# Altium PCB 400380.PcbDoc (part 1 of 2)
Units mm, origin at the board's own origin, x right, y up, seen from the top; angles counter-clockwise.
Board outline 48.52 x 76.32 mm, 4 copper layers (Top Layer, Mid-Layer 1, Mid-Layer 2, Bottom Layer), stack 1.542 mm thick; 122 components, 105 nets, 497 pads, 444 vias.
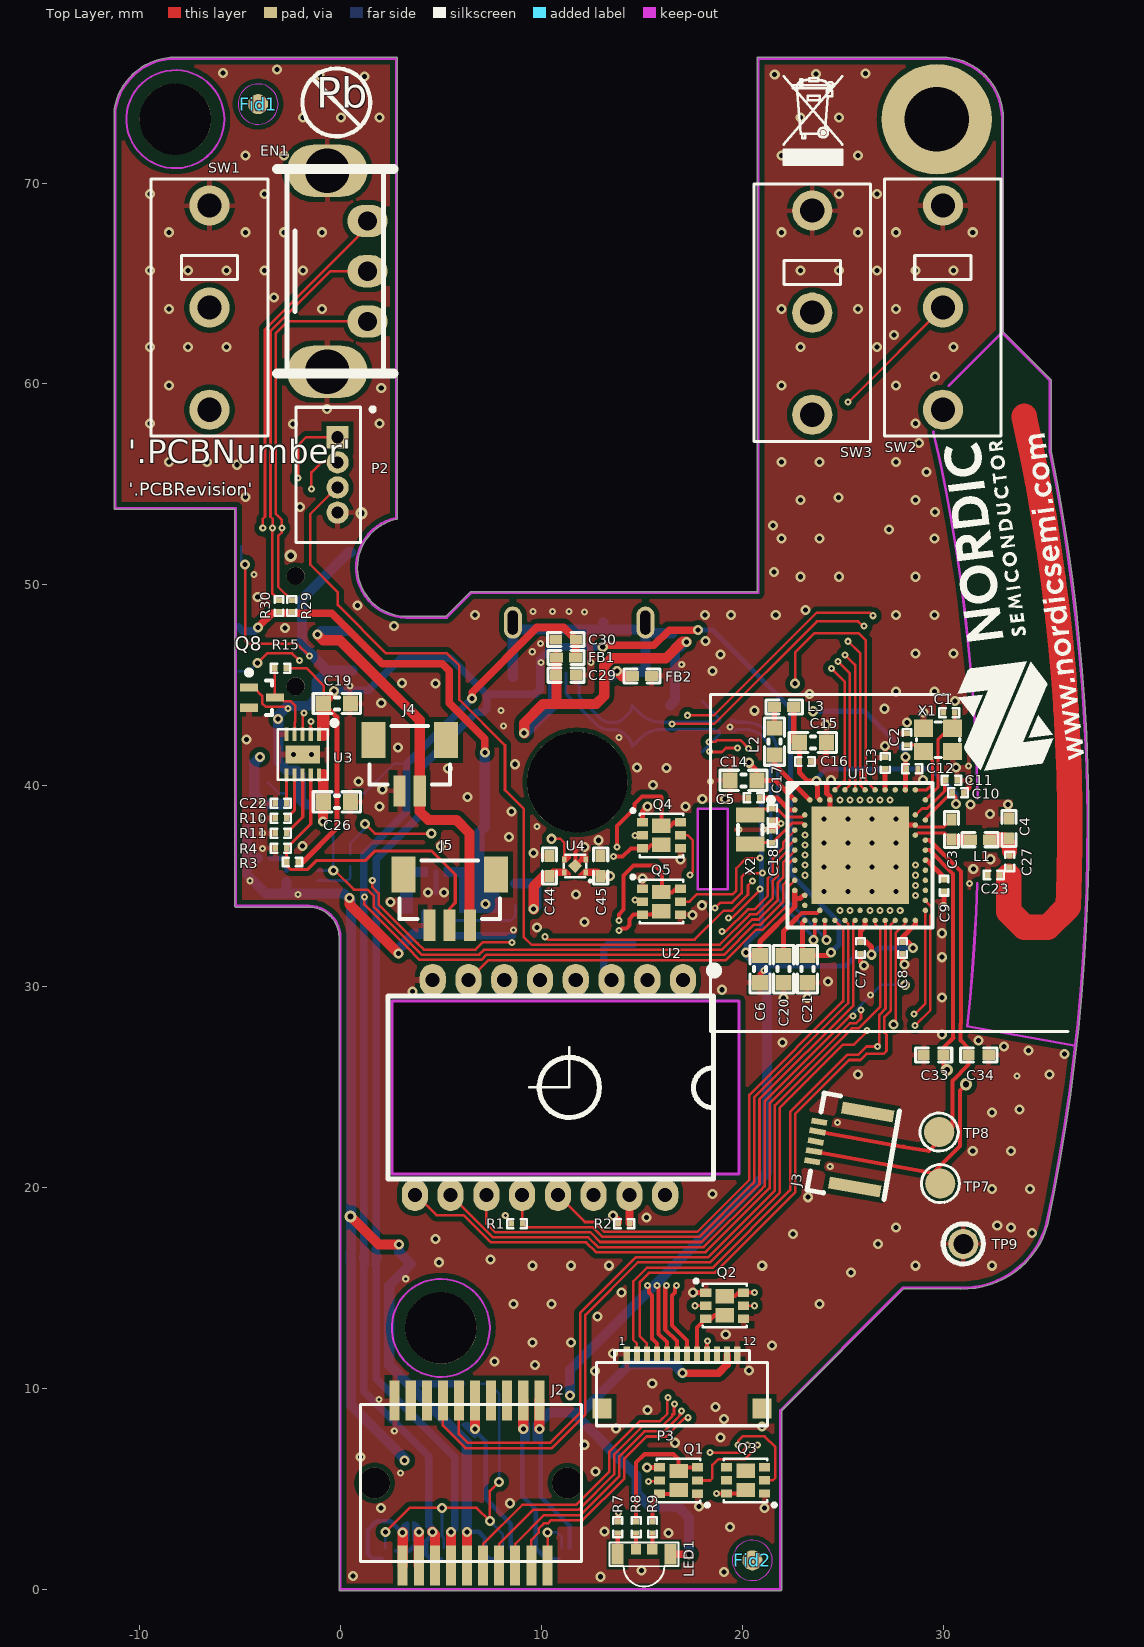
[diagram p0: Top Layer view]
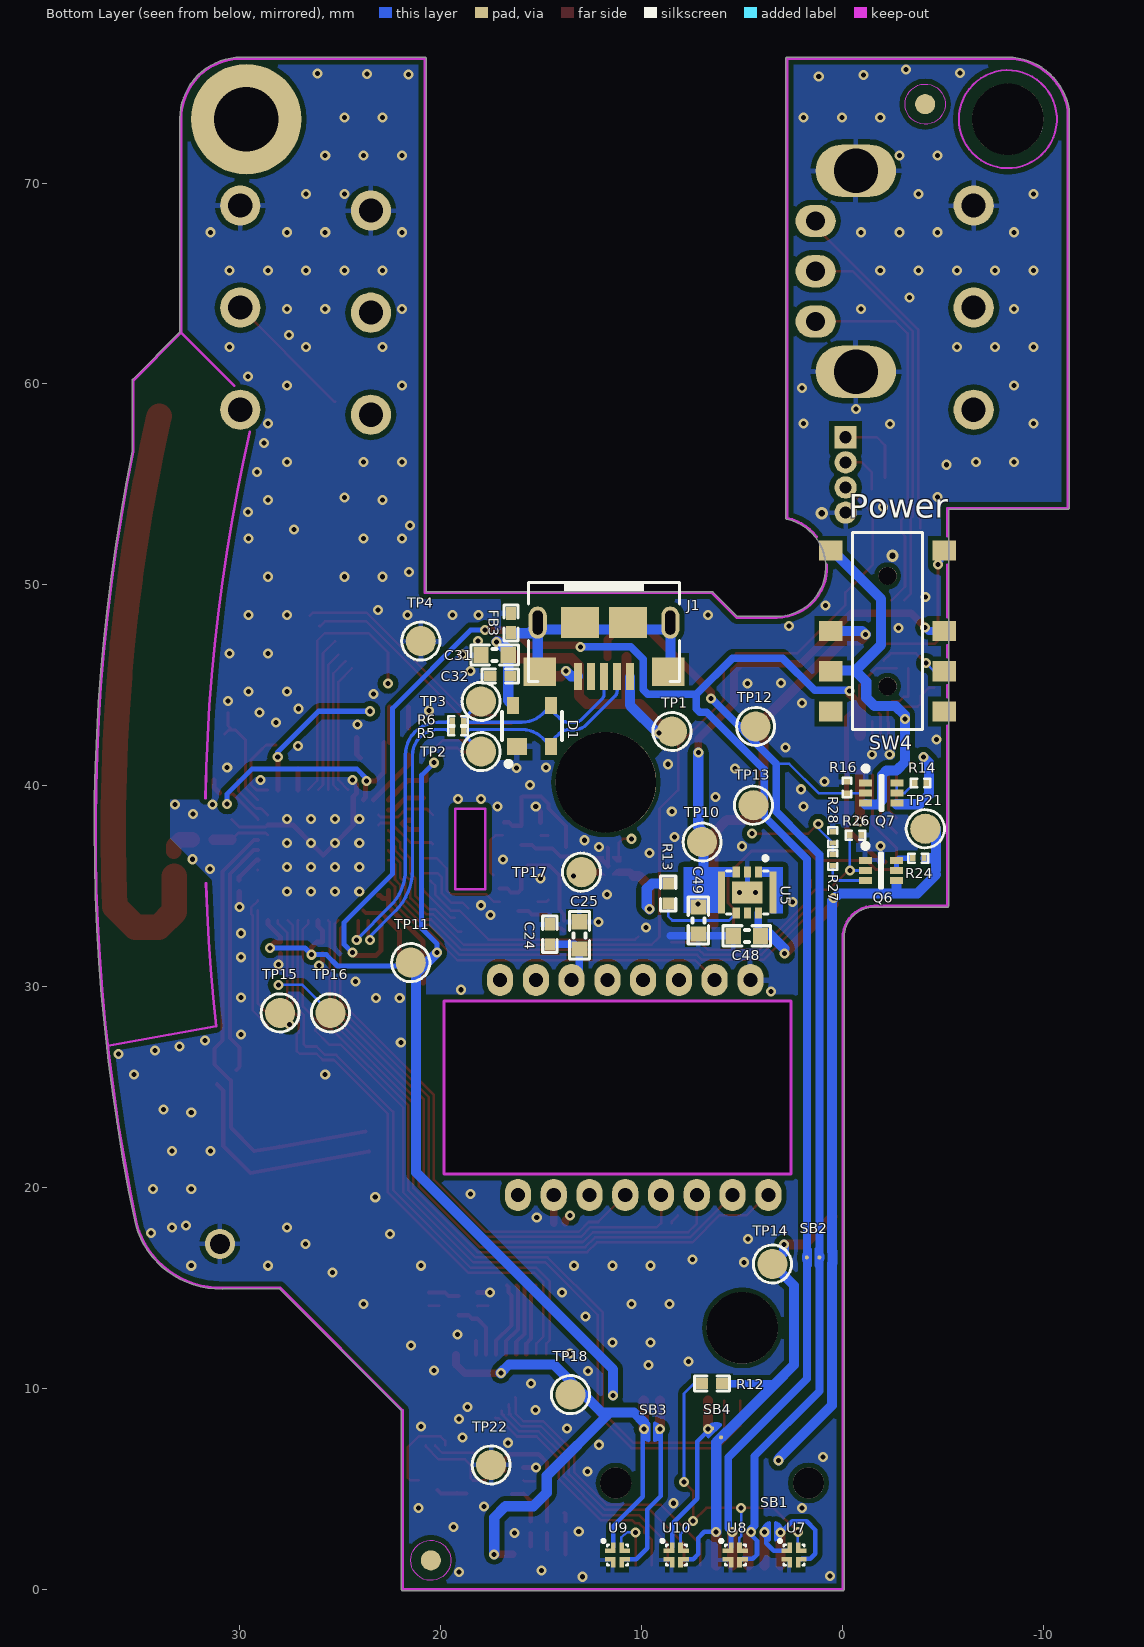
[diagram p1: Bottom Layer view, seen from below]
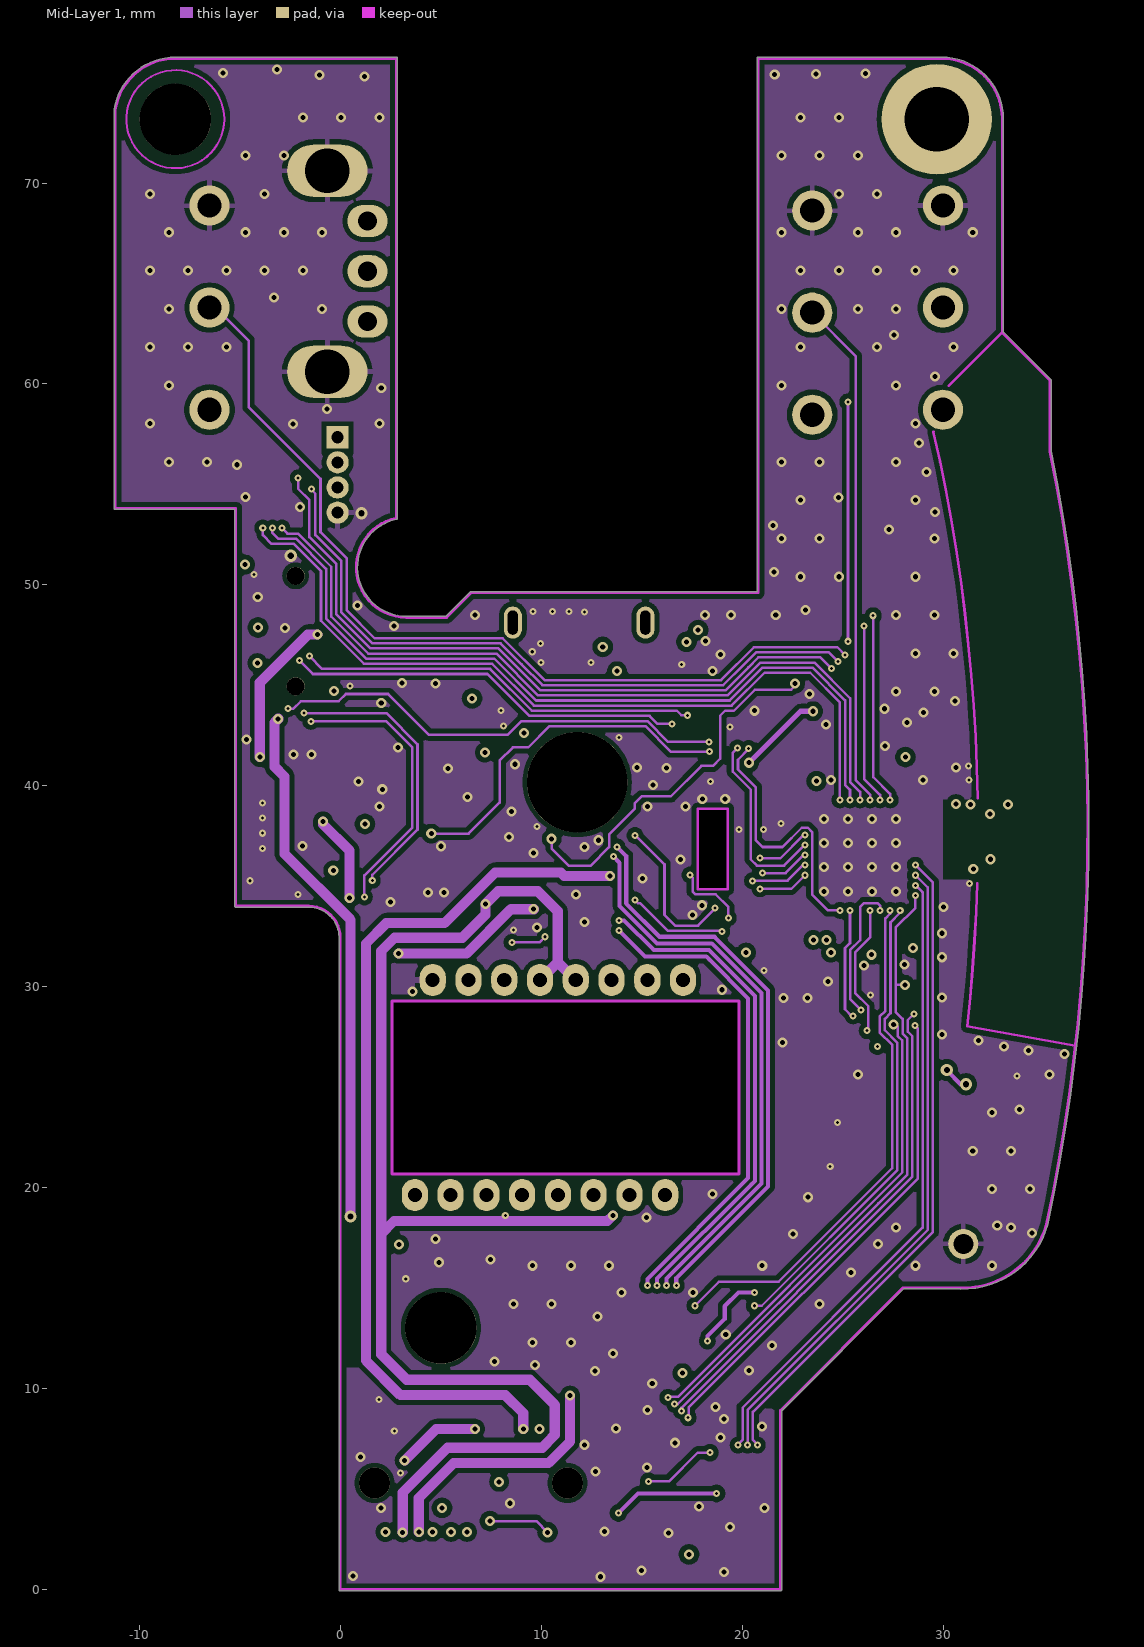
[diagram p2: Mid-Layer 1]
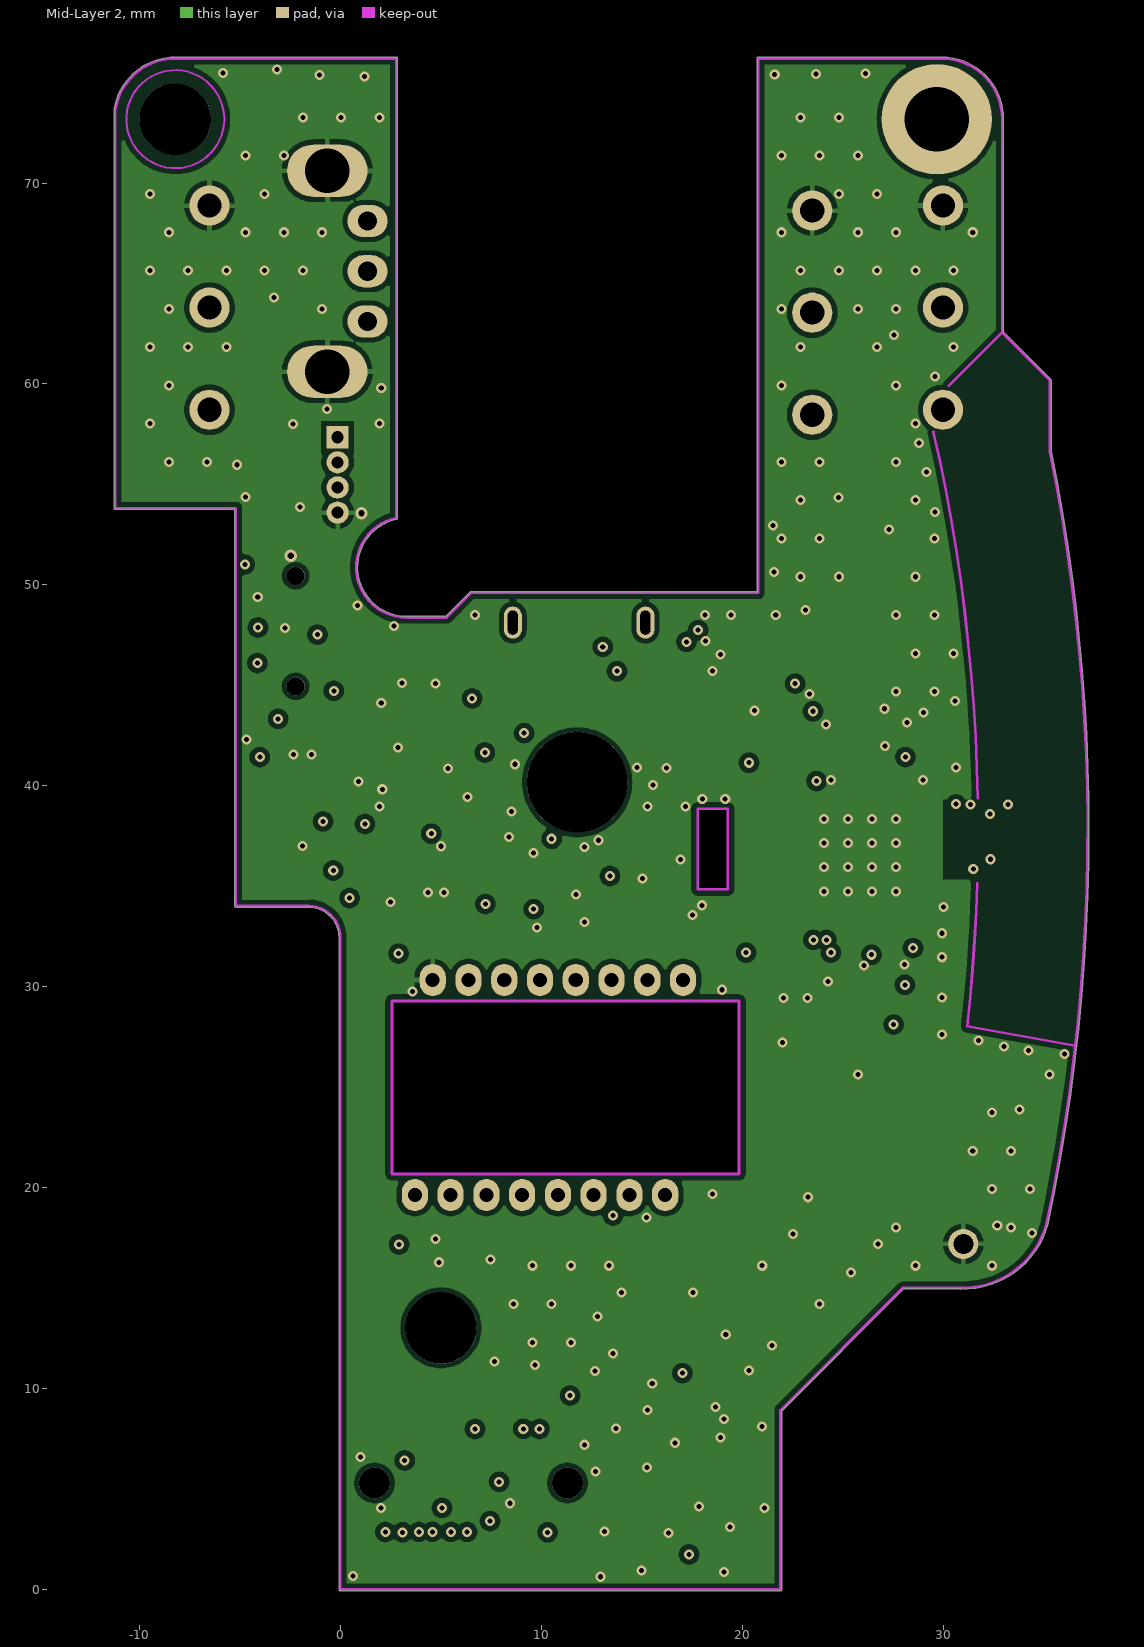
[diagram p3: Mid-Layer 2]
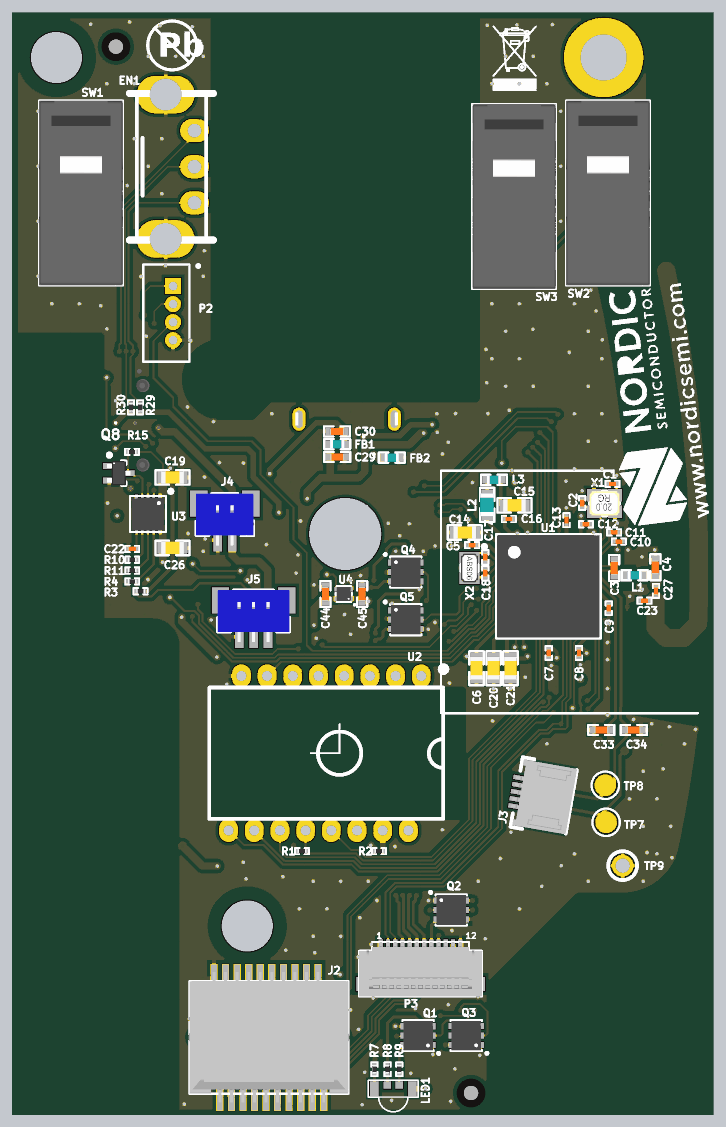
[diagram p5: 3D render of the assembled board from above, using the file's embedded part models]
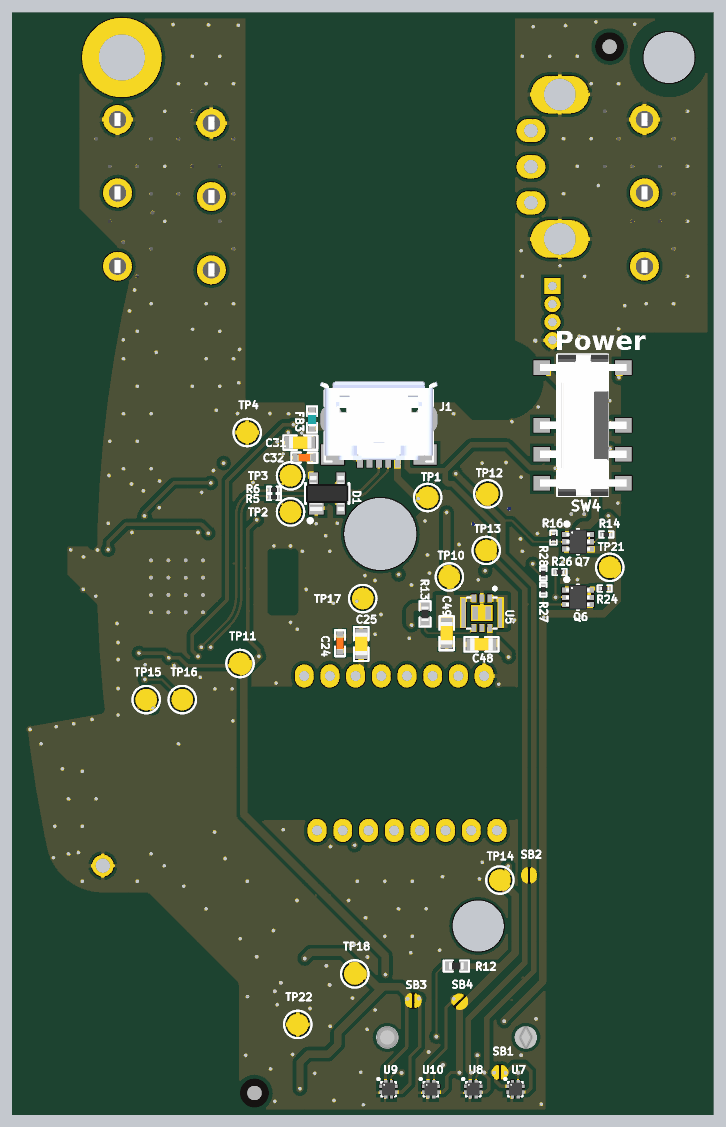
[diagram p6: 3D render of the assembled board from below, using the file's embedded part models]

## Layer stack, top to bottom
Top Solder: solder mask 0.0102, Solder Resist, Dk 3.5
Top Layer: signal copper 0.0356
Dielectric1: prepreg 0.1, FR-4, Dk 4.8
Mid-Layer 1: signal copper 0.0356
Dielectric2: core 1.2, FR-4, Dk 4.8
Mid-Layer 2: signal copper 0.0356
Dielectric3: prepreg 0.1, FR-4, Dk 4.8
Bottom Layer: signal copper 0.0356
Bottom Solder: solder mask 0.0102, Solder Resist, Dk 3.5

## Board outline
-5.2,33.956 -1.577,33.956 ccw(c-1.577,34.02) -1.558,33.959 ccw(c-1.538,34.02) -1.54,33.956 cw(c-1.577,32.443) -0.064,32.48 ccw(c0,32.482) -0.061,32.462 ccw(c0,32.443) -0.064,32.443 -0.064,0 ccw(c0,0) 0,-0.064 21.9,-0.064 ccw(c21.9,0) 21.964,0 21.964,8.894 28.026,14.956 30.378,14.956 30.879,14.956 ccw(c30.886,15.02) 30.885,14.956 ccw(c30.986,19.321) 35.194,18.155 35.195,18.159 ccw(c-57.806,37.826) 37.252,37.826 ccw(c-57.806,37.826) 35.37,56.647 35.37,60.182 ccw(c35.307,60.182) 35.352,60.227 32.995,62.584 32.995,73.197 cw(c32.931,73.197) 32.995,73.196 32.995,73.197 ccw(c29.931,73.197) 29.931,76.261 ccw(c29.931,76.197) 29.93,76.261 20.799,76.261 ccw(c20.798,76.197) 20.753,76.242 ccw(c20.798,76.197) 20.734,76.196 20.734,49.661 6.504,49.661 ccw(c6.504,49.597) 6.459,49.642 5.257,48.439 3.284,48.439 cw(c3.285,50.875) 2.783,53.259 cw(c3.285,50.875) 2.783,53.259 ccw(c2.77,53.322) 2.834,53.322 ccw(c2.77,53.322) 2.834,53.322 2.833,76.196 2.833,76.197 cw(c2.769,76.197) 2.833,76.196 2.833,76.197 ccw(c2.769,76.197) 2.798,76.254 ccw(c2.769,76.197) 2.769,76.261 -8.216,76.261 ccw(c-8.216,73.175) -11.264,73.658 ccw(c-11.201,73.648) -11.264,73.638 -11.264,53.82 ccw(c-11.2,53.82) -11.2,53.756 -5.264,53.756 -5.264,34.02 ccw(c-5.2,34.02)
cut-out: 19.284,38.85 19.284,34.85 17.784,34.85 17.784,38.85 19.284,38.85
cut-out: 19.834,29.287 19.834,20.687 2.574,20.687 2.574,29.287

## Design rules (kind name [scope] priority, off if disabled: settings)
Clearance ANT_Clerance [InNet('ANT')] p1: gap=0.127 ignorepadtopadclearanceinfootprint=FALSE except(0: Arc-Hole Track-Hole SMDPad-Hole THPad-Hole Via-Hole Fill-Hole Poly-Hole Region-Hole Text-Hole)
Clearance NPTH_Clerance [Not PadIsPlated And HoleSize > 0] p2: gap=0.229 ignorepadtopadclearanceinfootprint=FALSE
Clearance Polygon_Clearance [(InNamedPolygon('Top_Layer-GND')) or (InNamedPolygon('Bottom_Layer-GND')) or (InNamedPolygon('Mid_Layer_1-GND')) or (InNamedPolygon('Mid_Layer_2-GND'))] p3: gap=0.254 ignorepadtopadclearanceinfootprint=FALSE except(0: Arc-Hole Track-Hole SMDPad-Hole THPad-Hole Via-Hole Fill-Hole Poly-Hole Region-Hole Text-Hole)
Clearance [All] p4: gap=0.127 ignorepadtopadclearanceinfootprint=FALSE
ComponentClearance [All] p1 off: gap=0.254 collisioncheckmode=3 verticalgap=0.254 showdistances=FALSE
DiffPairsRouting [All] p1: maxlimit=0.193 minlimit=0.191 mostfreqgap=0.193 toplayer_minwidth=0.165 toplayer_maxwidth=0.165 toplayer_prefwidth=0.165 midlayer1_minwidth=0.165 midlayer1_maxwidth=0.165 midlayer1_prefwidth=0.165 midlayer2_minwidth=0.165 midlayer2_maxwidth=0.165 midlayer2_prefwidth=0.165 bottomlayer_minwidth=0.165 bottomlayer_maxwidth=0.165 bottomlayer_prefwidth=0.165 maxuncoupledlength=12.7
FabricationTestPointUsage TestPointUsage [All] p1: valid=0 allowmultiple=FALSE
FabricationTestpoint Testpoint [All] p1: side=3 testpointundercomponent=TRUE minsize=1.016 maxsize=2.54 preferedsize=1.524 minholesize=0 maxholesize=1.016 preferedholesize=0.813 testpointgrid=0.025 allowsidetop=TRUE allowsidebottom=TRUE usegrid=TRUE gridtolerance=0
Height [All] p1 off: minheight=0 maxheight=25.4 prefheight=12.7
HoleSize [All] p1: absolutevalues=TRUE maxlimit=5 minlimit=0.15 maxpercent=80.000 minpercent=20.000
MinimumAnnularRing [All] p1 off: minimumring=0.152
NetAntennae NetAntennae_ANT [InNet('ANT')] p1: netantennaetolerance=50
NetAntennae [All] p2: netantennaetolerance=0
PolygonConnect PolygonConnect_1 [isVia and innet(gnd) or isVia and innet('DEC')] p1: connectstyle=Direct reliefconductorwidth=0.254 reliefentries=4 polygonreliefangle="90 Angle" airgapwidth=0.254
PolygonConnect [All] p2: connectstyle=Relief reliefconductorwidth=0.254 reliefentries=4 polygonreliefangle="90 Angle" airgapwidth=0.254
RoutingVias [All] p1: holewidth=0.25 width=0.5 viastyle="Through Hole" minholewidth=0.15 minwidth=0.35 maxholewidth=0.305 maxwidth=0.61
SilkToSolderMaskClearance SilkscreenOverComponentPads [IsPad] p1: minsilkscreentomaskgap=0.254 clearancetoexposedcopper=TRUE
SolderMaskExpansion [All] p1: expansion=0.076
Width [All] p1: maxlimit=2.54 minlimit=0.127 preferedwidth=0.152
22 further rules are at their usual default settings.

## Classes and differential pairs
differential pair D*: +D*_P -D*_N
differential pair D: +D_P -D_N

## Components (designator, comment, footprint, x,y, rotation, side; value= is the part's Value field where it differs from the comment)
C1 "12pF" CAPC0603X03L_C 30.299,43.637 r180 top
C2 "12pF" CAPC0603X03L_C 28.198,42.316 r90 top
C3 "0.8pF" CAPC1005X04L 30.413,37.823 r270 top
C4 "0.5pF" CAPC1005X04L 33.268,37.868 r270 top
C5 "100nF" CAPC0603X03L_C 20.575,39.398 r180 top
C6 "4.7µF" CAPC1608X06L 20.88,30.872 r270 top
C7 "100nF" CAPC0603X03L_C 25.883,31.93 r270 top
C8 "100nF" CAPC0603X03L_C 27.977,31.93 r270 top
C9 "820pF" CAPC0603X03L_C 30.037,35.03 r270 top
C10 "N.C." CAPC0603X03L_C 30.734,39.646 r180 top
C11 "100pF" CAPC0603X03L_C 30.413,40.281 r0 top
C12 "100nF" CAPC0603X03L_C 28.46,40.843 r0 top
C13 "N.C." CAPC0603X03L_C 27.112,41.13 r90 top
C14 "1.0µF" CAPC1608X06L 20.062,40.272 r180 top
C15 "1.0µF" CAPC1608X06L 23.512,42.157 r180 top
C16 "47nF" CAPC0603X03L_C 23.115,41.209 r0 top
C17 "12pF" CAPC0603X03L_C 21.489,38.569 r270 top
C18 "12pF" CAPC0603X03L_C 21.489,37.464 r90 top
C19 "10µF" CAPC1608X06L -0.178,44.091 r180 top
C20 "4.7µF" CAPC1608X06L 22.062,30.872 r270 top
C21 "4.7µF" CAPC1608X06L 23.237,30.872 r270 top
C22 "100nF" CAPC0603X03L_C -2.967,39.137 r180 top
C23 "N.C." CAPC0603X03L_C 32.512,35.557 r180 top
C24 "100nF" CAPC1005X04L 14.58,32.61 r270 bottom
C25 "4.7µF" CAPC1608X06L 13.106,32.56 r270 bottom
C26 "10µF" CAPC1608X06L -0.178,39.205 r180 top
C27 "0.4pF" CAPC0603X03L_C 33.309,36.233 r270 top
C29 "10nF" CAPC1005X04L 11.23,45.504 r180 top
C30 "100nF" CAPC1005X04L 11.217,47.276 r0 top
C31 "10µF" CAPC1608X06L 17.323,46.504 r180 bottom
C32 "100nF" CAPC1005X04L 17.043,45.463 r180 bottom
C33 "560pF" CAPC1005X04L 29.524,26.601 r180 top
C34 "560pF" CAPC1005X04L 31.767,26.601 r180 top
C44 "1.0µF" CAPC1005X04L 10.414,36.014 r90 top
C45 "1.0µF" CAPC1005X04L 12.954,36.014 r90 top
C48 "10µF" CAPC1608X06L 4.775,32.534 r180 bottom
C49 "22µF" CAPC1608X06L 7.188,33.296 r90 bottom
D1 "PRTR5V0U2X" SOT190P230X110-4L 15.461,42.979 r90 bottom
EN1 "Scroll wheel encoder" M01_Scroll_Wheel_Encoder 1.347,65.61 r270 top locked
FB1 "120R/0.55A" INDC1005X04L 11.23,46.393 r0 top
FB2 "120R/0.55A" INDC1005X04L 15.011,45.463 r0 top
FB3 "120R/0.55A" INDC1005X04L 16.51,48.104 r90 bottom
Fid1 "Fiducial mark" Fiducial -4.1,73.925 r0 top
Fid2 "Fiducial mark" Fiducial 20.5,1.45 r0 top
J1 "MicroUSB-B" USB-Micro-B-RA-SMD-PiP 11.881,45.448 r270 bottom locked
J2 "Card Edge, 0.8mm" 10056847-101LF 6.5,5.3 r0 top
J3 "FPC 0.5mm RA SMD" FPC_05P-0.5mm-RA-SMD 23.482,21.315 r80 top
J4 "HDR-2, 1.0mm" BM02B-SRSS-TB 3.449,42.271 r180 top
J5 "HDR-3, 1.0mm" BM03B-SRSS-TB 5.44,35.582 r180 top
L1 "4.7nH" INDC1005X04L 31.836,37.315 r0 top
L2 "10µH" INDC1608X06L 21.612,42.197 r270 top
L3 "15nH" INDC1005X04L 22.087,43.922 r180 top
LED1 "LED RGB" L1204_RGB_SIDE 15.11,1.877 r90 top
P2 "HDR-4, 1.25mm" 1734598-4 -0.141,55.472 r270 top
P3 "FPC-12, 0.5mm" 10051922-1210ELF 17,11.7 r0 top
Q1 "TSM250N02DCQ RFG" DFN65P200X200X80_HS-6N 16.832,5.424 r180 top
Q2 "TSM250N02DCQ RFG" DFN65P200X200X80_HS-6N 19.126,14.126 r0 top
Q3 "TSM250N02DCQ RFG" DFN65P200X200X80_HS-6N 20.166,5.43 r180 top
Q4 "TSM250N02DCQ RFG" DFN65P200X200X80_HS-6N 15.979,37.535 r0 top
Q5 "TSM250N02DCQ RFG" DFN65P200X200X80_HS-6N 15.979,34.236 r0 top
Q6 "DMC2400UV" SOTFL50P162X60-6N -1.905,35.785 r180 bottom
Q7 "DMC2400UV" SOTFL50P162X60-6N -1.918,39.634 r180 bottom
Q8 "RE1C002UNTCL" SOTFL50P160X78-3N -3.901,44.384 r0 top
R1 "10k" RESC0603X03L_C 8.788,18.209 r180 top
R2 "39R" RESC0603X03L_C 14.122,18.209 r180 top
R3 "4k7" RESC0603X03L_C -2.388,36.207 r0 top
R4 "2k7" RESC0603X03L_C -2.967,36.893 r0 top
R5 "0R" RESC0603X03L_C 19.152,42.724 r180 bottom
R6 "0R" RESC0603X03L_C 19.152,43.234 r180 bottom
R7 "82R" RESC0603X03L_C 13.802,3.096 r270 top
R8 "100R" RESC0603X03L_C 14.716,3.096 r270 top
R9 "220R" RESC0603X03L_C 15.529,3.096 r270 top
R10 "5k6" RESC0603X03L_C -2.967,38.389 r0 top
R11 "13k" RESC0603X03L_C -2.967,37.641 r0 top
R12 "10k" RESC1005X04L 6.512,10.246 r180 bottom
R13 "1M0" RESC1005X04L 8.685,34.633 r90 bottom
R14 "1M0" RESC0603X03L_C -3.871,40.139 r180 bottom
R15 "100k" RESC0603X03L_C -2.981,45.857 r0 top
R16 "10k" RESC0603X03L_C -0.213,39.916 r270 bottom
R24 "1M0" RESC0603X03L_C -3.759,36.395 r0 bottom
R26 "1M0" RESC0603X03L_C -0.635,37.538 r180 bottom
R27 "1M5" RESC0603X03L_C 0.494,36.313 r90 bottom
R28 "180k" RESC0603X03L_C 0.494,37.436 r90 bottom
R29 "1M0" RESC0603X03L_C -2.42,48.943 r270 top
R30 "1M0" RESC0603X03L_C -3.055,48.943 r270 top
SB1 "Solderbridge" Solderbridge#1 3.497,2.892 r0 bottom
SB2 "Solderbridge" Solderbridge#2 1.476,16.527 r0 bottom
SB3 "Solderbridge" Solderbridge#3 9.508,7.843 r0 bottom
SB4 "Solderbridge" Solderbridge#4 6.278,7.795 r45 bottom
SW1 "SPDT" D2F-F -6.516,68.877 r270 top locked
SW2 "SPDT" D2F-F 29.984,68.877 r270 top locked
SW3 "SPDT" D2F-F 23.484,68.627 r270 top locked
SW4 "AYZ0203AGRLC" AYZ0203AGRLC -2.229,47.7 r90 bottom locked
TP1 "Ø1.5mm,SMD" TP_SMD_Ø1.5mm 8.5,42.7 r180 bottom
TP2 "Ø1.5mm,SMD" TP_SMD_Ø1.5mm 18,41.7 r180 bottom
TP3 "Ø1.5mm,SMD" TP_SMD_Ø1.5mm 18,44.2 r180 bottom
TP4 "Ø1.5mm,SMD" TP_SMD_Ø1.5mm 21,47.2 r180 bottom
TP7 "Ø1.5mm,SMD" TP_SMD_Ø1.5mm 29.855,20.202 r90 top
TP8 "Ø1.5mm,SMD" TP_SMD_Ø1.5mm 29.8,22.766 r90 top
TP9 "TP" TESTPAD-TH 31,17.2 r0 top
TP10 "Ø1.5mm,SMD" TP_SMD_Ø1.5mm 7,37.2 r180 bottom
TP11 "Ø1.5mm,SMD" TP_SMD_Ø1.5mm 21.5,31.2 r180 bottom
TP12 "Ø1.5mm,SMD" TP_SMD_Ø1.5mm 4.337,42.954 r180 bottom
TP13 "Ø1.5mm,SMD" TP_SMD_Ø1.5mm 4.447,39.034 r180 bottom
TP14 "Ø1.5mm,SMD" TP_SMD_Ø1.5mm 3.5,16.2 r180 bottom
TP15 "Ø1.5mm,SMD" TP_SMD_Ø1.5mm 28,28.7 r180 bottom
TP16 "Ø1.5mm,SMD" TP_SMD_Ø1.5mm 25.5,28.7 r180 bottom
TP17 "Ø1.5mm,SMD" TP_SMD_Ø1.5mm 13,35.7 r180 bottom
TP18 "Ø1.5mm,SMD" TP_SMD_Ø1.5mm 13.55,9.7 r180 bottom
TP21 "Ø1.5mm,SMD" TP_SMD_Ø1.5mm -4.11,37.862 r180 bottom
TP22 "Ø1.5mm,SMD" TP_SMD_Ø1.5mm 17.5,6.2 r180 bottom
U1 "nRF52840-QIAA" AQFN50P700X700X85_HS-74N 25.862,36.547 r0 top locked
U2 "PMW3360" PMW3360DM-T2QU 17.054,30.337 r0 top locked
U3 "AAT3693" QFN40P220X220X80_HS-11N -1.876,41.556 r270 top
U4 "NCP114AMX330" UDFN65P100X100X60_HS-5N 11.684,36.014 r180 top
U5 "XCL210C18" CL-2025 4.75,34.693 r270 bottom
U7 "MIC94080YFT" TMLF40P85X85X60-4N 2.423,1.716 r180 bottom
U8 "MIC94080YFT" TMLF40P85X85X60-4N 5.346,1.716 r180 bottom
U9 "MIC94080YFT" TMLF40P85X85X60-4N 11.211,1.716 r180 bottom
U10 "MIC94080YFT" TMLF40P85X85X60-4N 8.279,1.716 r180 bottom
X1 "32MHz" BT-XTAL_2016 29.745,42.287 r180 top
X2 "32.768kHz" XTAL_2012 20.397,37.82 r270 top

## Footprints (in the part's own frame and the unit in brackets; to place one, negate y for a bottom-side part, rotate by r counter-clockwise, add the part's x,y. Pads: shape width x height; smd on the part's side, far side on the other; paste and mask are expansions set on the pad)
1734598-4 [mm]
  rect 1.108x1.108 hole 0.6: 1(-1.875,0)
  round 1.108 hole 0.6: 2(-0.625,0) 3(0.625,0) 4(1.875,0)
  silkscreen extent -3.37,-2.07 3.37,1.85
10051922-1210ELF [mm]
  rect 0.95x1 smd: 0(-3.975,-2.7) 0(3.975,-2.7)
  rect 0.3x0.8 smd: 1(-2.75,0) 2(-2.25,0) 3(-1.75,0) 4(-1.25,0) 5(-0.75,0) 6(-0.25,0) 7(0.25,0) 8(0.75,0) 9(1.25,0) 10(1.75,0) 11(2.25,0) 12(2.75,0)
  silkscreen extent -4.25,-3.55 4.25,0.2, body extent -4.25,-3.55 4.25,0.2, height 1.27
10056847-101LF [mm]
  rect 0.5x2 smd paste-0.05 mask+0.025: 1(-3.4,-4.1) 2(-2.6,-4.1) 3(-1.8,-4.1) 4(-1,-4.1) 5(-0.2,-4.1) 6(0.6,-4.1) 7(1.4,-4.1) 8(2.2,-4.1) 9(3,-4.1) 10(3.8,-4.1) 11(3.4,4.1) 12(2.6,4.1) 13(1.8,4.1) 14(1,4.1) 15(0.2,4.1) 16(-0.6,4.1) 17(-1.4,4.1) 18(-2.2,4.1) 19(-3,4.1) 20(-3.8,4.1)
  round 1.55 hole 1.55 unplated mask+0: ""(-4.8,0) ""(4.8,0)
  silkscreen extent -5.5,-3.9 5.5,3.9, body extent -5.5,-4.5 5.5,4.53, height 5.28
AQFN50P700X700X85_HS-74N [mm] "AQFN, 73-Leads, Body 7.00x7.00mm, Pitch 0.50mm, Thermal Pad 4.95x4.95mm, IPC Medium Density"
  rect 4.85x4.85 smd mask+0.05: 74(0,0)
  round 0.275 smd paste+0.012 mask+0.05: A8(-1.25,3.25) A10(-0.75,3.25) A12(-0.25,3.25) A14(0.25,3.25) A16(0.75,3.25) A18(1.25,3.25) A20(1.75,3.25) A22(2.25,3.25) A23(2.75,3.25) AA24(3.25,-2.25) AB2(-2.75,-2.5) AC5(-2,-2.75) AC9(-1,-2.75) AC11(-0.5,-2.75) AC13(0,-2.75) AC15(0.5,-2.75) AC17(1,-2.75) AC19(1.5,-2.75) AC21(2,-2.75) AC24(3.25,-2.75) AD2(-2.75,-3.25) AD4(-2.25,-3.25) AD6(-1.75,-3.25) AD8(-1.25,-3.25) AD10(-0.75,-3.25) AD12(-0.25,-3.25) AD14(0.25,-3.25) AD16(0.75,-3.25) AD18(1.25,-3.25) AD20(1.75,-3.25) AD22(2.25,-3.25) AD23(2.75,-3.25) B1(-3.25,2.75) B3(-2.5,2.75) B5(-2,2.75) B7(-1.5,2.75) B9(-1,2.75) B11(-0.5,2.75) B13(0,2.75) B15(0.5,2.75) B17(1,2.75) B19(1.5,2.75) B24(3.25,2.75) C1(-3.25,2.25) D2(-2.75,2) D23(2.75,2) E24(3.25,1.75) F2(-2.75,1.5) F23(2.75,1.5) G1(-3.25,1.25) H2(-2.75,1) H23(2.75,1) J1(-3.25,0.75) J24(3.25,0.75) K2(-2.75,0.5) L1(-3.25,0.25) L24(3.25,0.25) M2(-2.75,0) N1(-3.25,-0.25) N24(3.25,-0.25) P2(-2.75,-0.5) P23(2.75,-0.5) R1(-3.25,-0.75) R24(3.25,-0.75) T2(-2.75,-1) T23(2.75,-1) U1(-3.25,-1.25) U24(3.25,-1.25) V23(2.75,-1.5) W1(-3.25,-1.75) W24(3.25,-1.75) Y2(-2.75,-2) Y23(2.75,-2)
  silkscreen extent -4.56,-3.6 3.6,3.6, body extent -3.55,-3.55 3.55,3.55, height 0.85
AYZ0203AGRLC [mm] "Slide Switch - DP3T, SMD, ON-ON-ON"
  round 0.9 hole 0.9 unplated mask+0: 0(-2.75,0) 0(2.75,0)
  rect 1x1.15 smd: 1(-4,2.825) 2(-2,2.825) 3(0,2.825) 4(4,2.825) 5(-4,-2.825) 6(-2,-2.825) 7(0,-2.825) 8(4,-2.825)
  silkscreen extent -4.9,-1.75 4.9,1.75, body extent -4.9,-3.05 4.9,2.95, height 2.5
BM02B-SRSS-TB [mm]
  rect 1.2x1.8 smd: 0(-1.8,0) 0(1.8,0)
  rect 0.6x1.55 smd: 1(0.5,2.525) 2(-0.5,2.525)
  silkscreen extent -2,-0.7 2,2.2, body extent -2,-0.7 2,2.9, height 4.25
BM03B-SRSS-TB [mm]
  rect 1.2x1.8 smd: 0(-2.3,0) 0(2.3,0)
  rect 0.6x1.55 smd: 1(1,2.525) 2(0,2.525) 3(-1,2.525)
  silkscreen extent -2.5,-0.7 2.5,2.2, body extent -2.5,-0.7 2.5,2.9, height 4.25
BT-XTAL_2016 [mm] "Crystal 2.0 x 1.6 mm"
  rect 0.95x0.85 smd: 1(-0.725,-0.575) 2(0.725,-0.575) 3(0.725,0.575) 4(-0.725,0.575)
  silkscreen extent -1.08,-0.88 1.08,0.88, body extent -1.05,-0.85 1.05,0.85, height 0.56
CAPC0603X03L_C [mm] "Chip Capacitor, 2-Leads, Body 0.6x0.3mm, IPC High Density"
  rect 0.27x0.3 smd: 1(-0.285,0) 2(0.285,0)
  silkscreen extent -0.49,-0.22 0.49,0.22, body extent -0.3,-0.15 0.31,0.15, height 0.3
CAPC1005X04L [mm] "Chip Capacitor, 2-Leads, Body 1.0x0.5mm, IPC High Density"
  rect 0.6x0.5 smd: 1(-0.5,0) 2(0.5,0)
  silkscreen extent -0.9,-0.35 0.9,0.35, body extent -0.51,-0.25 0.51,0.25, height 0.5
CAPC1608X06L [mm] "Chip Capacitor, 2-Leads, Body 1.6x0.8mm, IPC High Density"
  rect 0.75x0.8 smd: 1(-0.675,0) 2(0.675,0)
  silkscreen extent -1.17,-0.5 1.17,0.5, body extent -0.8,-0.43 0.8,0.43, height 0.8
CL-2025 [mm]
  rect 0.55x0.35 smd paste-0.025 mask+0.076: 1(-1.025,0.55) 2(-1.025,0) 3(-1.025,-0.55) 4(1.025,-0.55) 5(1.025,0) 6(1.025,0.55)
  rect 2.1x0.35 smd paste-0.038 mask+0.076: 7(0,1.275) 8(0,-1.275)
  rect 1.1x1.5 smd paste-5 mask+0.076: 9(0,0)
  silkscreen extent -1.8,-1.03 1.08,1.02, body extent -1,-1.25 1.01,1.25, height 1
D2F-F [mm]
  round 2 hole 1.2: 1(10.16,0) 2(0,0) 3(5.08,0)
  silkscreen extent -1.32,-2.9 11.48,2.9, body extent -1.32,-2.9 11.48,2.9, height 7
DFN65P200X200X80_HS-6N [mm] "DFN, 6-Leads, Body 2.00x2.00mm, Pitch 0.65mm, IPC Medium Density"
  rect 0.55x0.42 smd mask+0.055: 1(-0.945,0.65) 2(-0.945,0) 3(-0.945,-0.65) 4(0.945,-0.65) 5(0.945,0) 6(0.945,0.65)
  rect 0.92x0.71 smd mask+0.055: 3(0,-0.475) 6(0,0.475)
  silkscreen extent -1.48,-1.08 1.08,1.27, body extent -1.02,-1.02 1.02,1.02, height 0.8
Fiducial [mm] "Fiducial Mark"
  round 1 smd far side paste+0 mask+0.5: 0(0,0)
  round 1 smd paste+0 mask+0.5: 0(0,0)
  Top Layer keep-out circle w0.01: c0,0 r1
  Bottom Layer keep-out circle w0.01: c0,0 r1
FPC_05P-0.5mm-RA-SMD [mm] "FPC, 5-Leads, Pitch 0,5mm"
  rect 0.6x2.6 smd: 0(-0.9,-2.3) 0(2.9,-2.3)
  rect 0.3x0.8 smd: 1(0,0) 2(0.5,0) 3(1,0) 4(1.5,0) 5(2,0)
  silkscreen extent -1.45,-3.85 3.45,0, body extent -1.3,-3.85 3.3,0.2, height 1.2
INDC1005X04L [mm] "Chip Inductor, 2-Leads, Body 1.0x0.5mm, IPC High Density"
  rect 0.65x0.5 smd: 1(-0.475,0) 2(0.475,0)
  silkscreen extent -0.9,-0.35 0.9,0.35, body extent -0.5,-0.3 0.5,0.3, height 0.5
INDC1608X06L [mm] "Chip Inductor, 2-Leads, Body 1.6x0.8mm, IPC High Density"
  rect 0.75x0.8 smd: 1(-0.675,0) 2(0.675,0)
  silkscreen extent -1.17,-0.5 1.17,0.5, body extent -0.8,-0.48 0.8,0.48, height 0.8
L1204_RGB_SIDE [mil] "Optek's OVSRRGBCC3 RGB full-color 1204 SMD, RGB LED"
  rect 20x20 smd: 1(5,-16) 2(5,16)
  rect 40x24 smd: 3(-5,52) 4(-5,-52)
  silkscreen extent -68,-68 18,68
M01_Scroll_Wheel_Encoder [mm]
  oval 1.6x2 hole 0.95: 1(-2.5,0) 2(0,0) 3(2.5,0)
  oval 2.6x4 hole 2.2: 4(-5,-2) 5(5,-2)
  silkscreen extent -5.08,-4.5 5.08,1.3
PMW3360DM-T2QU [mm]
  oval 1.3x1.6 hole 0.7: 1(0,0) 2(-1.78,0) 3(-3.56,0) 4(-5.34,0) 5(-7.12,0) 6(-8.9,0) 7(-10.68,0) 8(-12.46,0) 9(-13.35,-10.7) 10(-11.57,-10.7) 11(-9.79,-10.7) 12(-8.01,-10.7) 13(-6.23,-10.7) 14(-4.45,-10.7) 15(-2.67,-10.7) 16(-0.89,-10.7)
  Keep-Out Layer lines w0.15: -14.48,-9.65 2.78,-9.65 2.78,-1.05 -14.48,-1.05 -14.48,-9.65
  silkscreen extent -14.68,-9.9 1.64,0.57
QFN40P220X220X80_HS-11N [mm] "QFN, 10-Leads, Body 2,20x2,20mm, Pitch 0,40mm, Thermal Pad 0,90x1,70mm, IPC Medium Density"
  rect 0.66x0.2 smd: 1(-1.015,0.8) 2(-1.015,0.4) 3(-1.015,0) 4(-1.015,-0.4) 5(-1.015,-0.8) 6(1.015,-0.8) 7(1.015,-0.4) 8(1.015,0) 9(1.015,0.4) 10(1.015,0.8)
  rect 0.9x1.7 smd: 11(0,0)
  silkscreen extent -1.7,-1.25 1.25,1.7, body extent -1.13,-1.12 1.13,1.12, height 0.8
RESC0603X03L_C [mm] "Chip Resistor, 2-Leads, Body 0.6x0.3mm, IPC High Density"
  rect 0.27x0.3 smd: 1(-0.285,0) 2(0.285,0)
  silkscreen extent -0.49,-0.22 0.49,0.22, body extent -0.3,-0.15 0.3,0.15, height 0.23
RESC1005X04L [mm] "Chip Resistor, 2-Leads, Body 1.0x0.5mm, IPC High Density"
  rect 0.6x0.55 smd: 1(-0.5,0) 2(0.5,0)
  silkscreen extent -0.87,-0.38 0.88,0.38, body extent -0.5,-0.25 0.5,0.25, height 0.3
Solderbridge#1 [mm]
  round 0.2 smd paste-10: 1(-0.312,0) 2(0.312,0)
  Top Layer region: 0.077,0.432 0.152,0.505 0.271,0.467 0.335,0.424 0.409,0.351 0.462,0.292 0.521,0.193 0.549,0.099 0.544,-0.122 0.518,-0.193 0.434,-0.33 0.351,-0.411 0.259,-0.469 0.157,-0.5 0.107,-0.483 0.077,-0.43
  Top Layer region: -0.077,-0.432 -0.152,-0.505 -0.271,-0.467 -0.335,-0.424 -0.409,-0.351 -0.462,-0.292 -0.521,-0.193 -0.549,-0.099 -0.544,0.122 -0.518,0.193 -0.434,0.33 -0.351,0.411 -0.259,0.469 -0.157,0.5 -0.107,0.483 -0.077,0.43
  Top Layer lines w0.152: -0.153,0.431 ccw(c-0.042,0) -0.487,0 ccw(c-0.042,0) -0.153,-0.431 ; 0.153,0.431 cw(c0.042,0) 0.312,0.353 cw(c0.042,0) 0.153,-0.431
Solderbridge#2 [mm]
  round 0.2 smd paste-10: 1(-0.312,0) 2(0.312,0)
  Top Layer region: 0.077,0.432 0.152,0.505 0.271,0.467 0.335,0.424 0.409,0.351 0.462,0.292 0.521,0.193 0.549,0.099 0.544,-0.122 0.518,-0.193 0.434,-0.33 0.351,-0.411 0.259,-0.469 0.157,-0.5 0.107,-0.483 0.077,-0.43
  Top Layer region: -0.077,-0.432 -0.152,-0.505 -0.271,-0.467 -0.335,-0.424 -0.409,-0.351 -0.462,-0.292 -0.521,-0.193 -0.549,-0.099 -0.544,0.122 -0.518,0.193 -0.434,0.33 -0.351,0.411 -0.259,0.469 -0.157,0.5 -0.107,0.483 -0.077,0.43
  Top Layer lines w0.152: -0.153,0.431 ccw(c-0.042,0) -0.319,0.348 ccw(c-0.042,0) -0.392,0.275 ccw(c-0.042,0) -0.392,-0.275 ccw(c-0.042,0) -0.319,-0.348 ccw(c-0.042,0) -0.153,-0.431 ; 0.153,0.431 cw(c0.042,0) 0.302,0.361 cw(c0.042,0) 0.316,0.35 cw(c0.042,0) 0.37,0.3 cw(c0.042,0) 0.378,0.292 cw(c0.042,0) 0.484,0.049 cw(c0.042,0) 0.37,-0.3 cw(c0.042,0) 0.316,-0.35 cw(c0.042,0) 0.302,-0.361 cw(c0.042,0) 0.153,-0.431
Solderbridge#3 [mm]
  round 0.2 smd paste-10: 1(-0.312,0) 2(0.312,0)
  Top Layer region: -0.077,-0.432 -0.152,-0.505 -0.271,-0.467 -0.335,-0.424 -0.409,-0.351 -0.462,-0.292 -0.521,-0.193 -0.549,-0.099 -0.544,0.122 -0.518,0.193 -0.434,0.33 -0.351,0.411 -0.259,0.469 -0.157,0.5 -0.107,0.483 -0.077,0.43
  Top Layer region: 0.077,0.432 0.152,0.505 0.271,0.467 0.335,0.424 0.409,0.351 0.462,0.292 0.521,0.193 0.549,0.099 0.544,-0.122 0.518,-0.193 0.434,-0.33 0.351,-0.411 0.259,-0.469 0.157,-0.5 0.107,-0.483 0.077,-0.43
  Top Layer lines w0.152: -0.153,0.431 ccw(c-0.042,0) -0.452,0.173 ccw(c-0.042,0) -0.452,-0.173 ccw(c-0.042,0) -0.153,-0.431 ; 0.153,0.431 cw(c0.042,0) 0.391,0.275 cw(c0.042,0) 0.454,0.169 cw(c0.042,0) 0.454,-0.169 cw(c0.042,0) 0.392,-0.274 cw(c0.042,0) 0.391,-0.275 cw(c0.042,0) 0.153,-0.431
Solderbridge#4 [mm]
  round 0.2 smd paste-10: 1(-0.312,0) 2(0.312,0)
  Top Layer region: -0.077,-0.432 -0.152,-0.505 -0.271,-0.467 -0.335,-0.424 -0.409,-0.351 -0.462,-0.292 -0.521,-0.193 -0.549,-0.099 -0.544,0.122 -0.518,0.193 -0.434,0.33 -0.351,0.411 -0.259,0.469 -0.157,0.5 -0.107,0.483 -0.077,0.43
  Top Layer region: 0.077,0.432 0.152,0.505 0.271,0.467 0.335,0.424 0.409,0.351 0.462,0.292 0.521,0.193 0.549,0.099 0.544,-0.122 0.518,-0.193 0.434,-0.33 0.351,-0.411 0.259,-0.469 0.157,-0.5 0.107,-0.483 0.077,-0.43
  Top Layer lines w0.152: -0.153,-0.431 cw(c-0.042,0) -0.326,-0.342 cw(c-0.042,0) -0.378,-0.291 cw(c-0.042,0) -0.39,-0.277 cw(c-0.042,0) -0.431,0.216 cw(c-0.042,0) -0.427,0.224 cw(c-0.042,0) -0.326,0.342 cw(c-0.042,0) -0.153,0.431 ; 0.153,-0.431 ccw(c0.042,0) 0.312,0.353 ccw(c0.042,0) 0.153,0.431
SOT190P230X110-4L [mm] "SOT143, 4-Leads, Body 3.0x2.5mm (max), Pitch 1.90mm, IPC High Density"
  rect 0.85x1 smd: 1(-1.025,0.75)
  rect 0.85x0.6 smd: 2(-1.025,-0.95) 3(1.025,-0.95) 4(1.025,0.95)
  silkscreen extent -2.01,-1.5 0.7,1.5, body extent -1.21,-1.46 1.21,1.46, height 1
SOTFL50P160X78-3N [mm] "SOTFL, 3-Leads, Body 1.60x1.60mm, Pitch 0.50mm, IPC Medium Density"
  rect 0.9x0.4 smd: 1(-0.65,0.5) 2(-0.65,-0.5) 3(0.65,0)
  silkscreen extent -0.77,-0.85 0.49,1.37, body extent -0.8,-0.85 0.8,0.85, height 0.78
SOTFL50P162X60-6N [mm] "SOTFL, 6-Leads, Body 1.60x1.63mm, Pitch 0.50mm, IPC Medium Density"
  rect 0.65x0.35 smd: 1(-0.775,0.5) 2(-0.775,0) 3(-0.775,-0.5) 4(0.775,-0.5) 5(0.775,0) 6(0.775,0.5)
  silkscreen extent -0.9,-0.85 0.05,1.35, body extent -0.81,-0.85 0.81,0.85, height 0.6
TESTPAD-TH [mm]
  round 1.5 hole 1: 1(0,0)
  silkscreen extent -1,-1 1,1
TMLF40P85X85X60-4N [mm] "TMLF, 4-Leads, Body 0.85x0.85mm, Pitch 0.40mm, IPC Medium Density"
  rect 0.54x0.23 smd mask+0.06: 1(-0.36,0.205) 2(-0.36,-0.205) 3(0.36,-0.205) 4(0.36,0.205)
  rect 0.23x0.54 smd mask+0.06: 1(-0.205,0.36) 2(-0.205,-0.36) 3(0.205,-0.36) 4(0.205,0.36)
  silkscreen extent -0.75,-0.51 0.51,0.75, body extent -0.45,-0.45 0.45,0.45, height 0.6
TP_SMD_Ø1.5mm [mm]
  round 1.5 smd paste-5: 1(0,0)
  silkscreen extent -0.95,-0.95 0.95,0.95
UDFN65P100X100X60_HS-5N [mm] "UDFN, 4-Leads, Body 1.00x1.00mmx0.60mm, Pitch 0.65mm"
  rect 0.23x0.3 smd paste-1 mask+0: 1(-0.535,0.325) 2(-0.535,-0.325) 3(0.535,-0.325) 4(0.535,0.325)
  rect 0.5x0.5 smd rot 135 mask+0.05: 5(0,0)
  Top Layer region: -0.65,0.475 -0.12,0.475 -0.42,0.175 -0.65,0.175
  Top Layer region: 0.65,-0.475 0.22,-0.475 0.22,-0.375 0.42,-0.175 0.65,-0.175
  Top Layer region: 0.65,0.475 0.22,0.475 0.22,0.375 0.42,0.175 0.65,0.175
  Top Layer region: -0.65,-0.475 -0.22,-0.475 -0.22,-0.375 -0.42,-0.175 -0.65,-0.175
  silkscreen extent -0.8,-0.56 0.56,0.8, body extent -0.5,-0.5 0.5,0.5, height 0.6
USB-Micro-B-RA-SMD-PiP [mm] "Micro USB B SMT"
  rect 1.35x0.4 smd: 1(0,1.3) 2(0,0.65) 3(0,0) 4(0,-0.65) 5(0,-1.3)
  oval 1.6x0.9 hole 0.5 slot 1.2 at 0 deg: 6(-2.675,-3.3) 6(-2.675,3.3)
  oval 2x1.5 on Bottom Paste: 6(-2.675,-3.3) 6(-2.675,3.3)
  rect 1.55x1.9 smd: 6(-2.675,-1.2) 6(-2.675,1.2)
  rect 1.4x1.6 smd: 6(-0.225,-3.2) 6(-0.225,3.2)
  silkscreen extent -4.75,-3.75 0.25,3.75, body extent -5.28,-4.1 0.15,4.1, height 2.72
XTAL_2012 [mm] "XTAL SMD 2.0 x 1.2 mm"
  rect 0.75x1.4 smd: 1(-0.725,0) 2(0.725,0)
  silkscreen extent -0.24,-0.6 0.24,0.6, body extent -1,-0.61 1,0.61, height 0.6

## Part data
C1 C2 C17 C18: library part C0201-12p, "Capacitor, NP0, ±2%", Part number IPS=00000007848
C3: library part C0402-0.8p, "Capacitor, NP0, ±5%", Part number IPS=00000007782
C4: library part C0402-0.5p, "Capacitor, NP0, ±0.05pF", Part number IPS=N.A., Supplier Part Number 1=490-11250-1-ND
C5 C7 C8 C12 C22: library part C0201-100n, "Capacitor, X5R, ±10%", Part number IPS=00000001248
C6 C20: library part C0603-4µ7-6.3V-X7R, "Capacitor, X7R, ±10%", Manufacturer=Samsung, Manufacturer Part Number=CL10B475KQ8NQNC, Part number IPS=N.A., Supplier Part Number 1=1276-2087-1-ND
C9: library part C0201-820p, "Capacitor, X7R, ±10%", Part number IPS=00000001249
C10 C13 C23: library part C0201-N.C., "Not mounted", Part number IPS=N.A.
C11: library part C0201-100p, "Capacitor, NP0, ±2%", Part number IPS=00000007853
C14 C15: library part C0603-1µ0, "Capacitor, X7R, ±10%", Part number IPS=00000000616
C16: library part C0201-47n, "Capacitor, X5R, ±10%", Part number IPS=00000001250
C19 C26: library part C0603-10µF-25V, "Capacitor, 0603, 25V, X5R", Part number IPS=N.A.
C21: library part C0603-4µ7-10V-X7S, "Capacitor, X7S, ±10%", Part number IPS=N.A., Supplier Part Number 1=445-14258-1-ND
C24 C30 C32: library part C0402-100n, "Capacitor, X7R, ±10%", Part number IPS=00000005296
C25: library part C0603-4µ7, "Capacitor, X5R, ±10%", Part number IPS=00000007783
C27: library part C0201-0.4p, "Capacitor, NP0, ±0.05pF", Part number IPS=N.A.
C29: library part C0402-10n, "Capacitor, X7R, ±10%", Part number IPS=00000007784
C31 C48: library part C0603-10µ, "Capacitor, X5R, ±20%", Part number IPS=00000007785
C33 C34: library part C0402-560p, "Capacitor, NP0, ±5%", Part number IPS=N.A.
C44 C45: library part C0402-1µ0, "Capacitor, X5R, ±5%", Part number IPS=00000007786, Supplier Part Number 1=1276-1444-1-ND
C49: library part C0603-22µ-6.3V, "CAP CER 22UF 6.3V 20% X5R 0603", Manufacturer=Samsung, Manufacturer Part Number=CL10A226MQ8NRNC, Part number IPS=00000007787, Supplier Part Number 1=1276-1193-1-ND
D1: "Ultra low capacitance double rail-to-rail ESD protection diode", Manufacturer=NXP, Part number IPS=00000009951, Supplier Part Number 1=568-4140-1-ND
EN1: library part "M01_Scroll_wheel_encoder, 10.5mm", "Scroll wheel encoder, 10.5mm", Part number IPS=N.A.
FB1 FB2 FB3: library part FB0402-120R@100M-500mA, "Ferrite Bead, 120 Ohm @ 100MHz, 500mA, 250 mOhm Max", Manufacturer=Murata, Manufacturer Part Number=BLM15AG121SN1D, Part number IPS=N.A., Supplier Part Number 1=490-1005-1-ND
Fid1 Fid2: library part Fid-Mark, "Fiducial Mark", Part number IPS=N.A.
J1: library part USB-Micro-B-RA-SMD-PiP, "MicroUSB-B-SMT", Manufacturer="Allen Creations Corp.", Manufacturer Part Number=AJU55-BS2111-L, Part number IPS=00000007790
J2: library part 10056847-101LF, "0.8mm pitch, dual edge, right angle, SMD, card edge connector", Manufacturer=FCI, Part number IPS=N.A., Supplier Part Number 1=609-4943-1-ND
J3: library part FPC_05P-0.5mm-RA-SMD, "0.5mm FPC, 5P,Right Angle SMT,Double Contact,H=1.2mm,White, Tin plated", Manufacturer=W-CON, Manufacturer Part Number=5141-05RZDNWR01, Part number IPS=00000007792
J4: library part BM02B-SRSS-TB, "1.0mm pitch top entry SMD wire to board connector", Manufacturer=JST, Part number IPS=N.A., Supplier Part Number 1=455-1788-1-ND
J5: library part BM03B-SRSS-TB, "1.0mm pitch top entry SMD wire to board connector", Manufacturer=JST, Part number IPS=N.A., Supplier Part Number 1=455-1789-1-ND
L1: library part L0402-4n7, "Inductor, 160mA, ±0.1nH", Manufacturer=Murata, Manufacturer Part Number=LQP15MN4N7B02D, Part number IPS=N.A., Supplier Part Number 1=490-1132-1-ND
L2: library part L0603-10µ, "Inductor, 80mA, ±10%", Manufacturer="Taiyo Yuden", Manufacturer Part Number=LBMF1608T100K, Part number IPS=00000007794, Supplier Part Number 1=587-1714-1-ND
L3: library part L0402-15n, "Inductor, 320mA, ±5%", Manufacturer="Taiyo Yuden", Manufacturer Part Number=HK100515NJ-T, Part number IPS=00000001262, Supplier Part Number 1=587-1521-1-ND
LED1: library part Led_RGB_Side, "Optek, Side mounted RGB 1204 SMD LED", Manufacturer=Optek, Manufacturer Part Number=OVSRRGBCC3, Part number IPS=N.A., Supplier Part Number 1=365-1410-1-ND
P2: library part 1734598-4, "Connector Header Through Hole 4 position 0.049\" (1.25mm)", Manufacturer="TE Connectivity", Part number IPS=N.A., Supplier Part Number 1=A99916-ND
P3: library part 10051922-1210ELF, "0.5mm pitch, bottom side contact, side entry SMD FPC connector", Manufacturer=FCI, Part number IPS=N.A., Supplier Part Number 1=609-1236-1-ND
Q1 Q2 Q3 Q4 Q5: "Dual N Ch MOFET, 5.8A, 55mOhm max, 620mW", Manufacturer="Taiwan Semiconductor", Part number IPS=N.A., Supplier Part Number 1=TSM250N02DCQRFGCT-ND
Q6 Q7: "Dual N & P Ch MOFET, 1.03A/0.7A, 480mOhm, 450mW", Manufacturer="Diodes Incorporated", Part number IPS=00000007803, Supplier Part Number 1=DMC2400UV-7DICT-ND
Q8: "MOSFET N-CH 20V 0.2A EMT3", Manufacturer="Rohm Semiconductor", Part number IPS=N.A., Supplier Part Number 1=RE1C002UNTCLCT-ND
R1 R16: library part R0201-10k, "Resistor, ±1%, 0.05W", Part number IPS=00000001255
R2: library part R0201-39R, "Resistor, ±1%, 0.05W", Part number IPS=N.A.
R3: library part R0201-4k7, "Resistor, ±1%, 0.05W", Part number IPS=N.A.
R4: library part R0201-2k7, "Resistor, ±1%, 0.05W", Part number IPS=N.A.
R5 R6: library part R0201-0R, "Resistor, ±5%, 0.05W", Part number IPS=00000003245
R7: library part R0201-82R, "Resistor, ±1%, 0.05W", Part number IPS=N.A.
R8: library part R0201-100, "Resistor, ±1%, 0.05W", Part number IPS=N.A.
R9: library part R0201-220, "Resistor, ±1%, 0.05W", Part number IPS=00000000863
R10: library part R0201-5k6, "Resistor, ±1%, 0.05W", Part number IPS=N.A.
R11: library part R0201-13k, "Resistor, ±1%, 0.05W", Part number IPS=N.A.
R12: library part R0402-10k, "Resistor, ±1%, 0.063W", Part number IPS=00000002093, Supplier Part Number 1=173-8864
R13: library part R0402-1M0, "Resistor, ±1%, 0.063W", Part number IPS=00000006807
R14 R24 R26 R29 R30: library part R0201-1M0, "Resistor, ±1%, 0.05W", Part number IPS=N.A.
R15: library part R0201-100k, "Resistor, ±1%, 0.05W", Part number IPS=00000001419
R27: library part R0201-1M5, "Resistor, ±1%, 0.05W", Part number IPS=N.A.
R28: library part R0201-180k, "Resistor, ±1%, 0.05W", Part number IPS=N.A.
SB1 SB2 SB3 SB4: Part number IPS=N.A.
SW1 SW2 SW3: library part D2F-F, "SWITCH SNAP ACTION SPDT 1A 125V", Manufacturer=Omron, Part number IPS=N.A., Supplier Part Number 1=SW503-ND
SW4: "Slide Switch DP3T Surface Mount, 100mA, 12V", Manufacturer="C&K Components", Part number IPS=N.A., Supplier Part Number 1=401-2015-1-ND
TP1 TP2 TP3 TP4 TP7 TP8 TP10 TP11 TP12 TP13 TP14 TP15 TP16 TP17 TP18 TP21 TP22: library part TP_SMD_Ø1.5MM, "1.0mm circular SMD testpad", Manufacturer="Nordic Semiconductor", Part number IPS=N.A.
TP9: library part "Testpoint TH", "Testpoint, through hole", Part number IPS=N.A.
U1: library part nRF52840-QIAAD0, "Multi-protocol Bluetooth Low Energy, IEEE 802.15.4, ANT and 2.4GHz proprietary system-on-chip", Manufacturer="Nordic Semiconductor", Part number IPS=N.A.
U2: library part PMW3360DM-T2QU, "Optical Gaming Navigation Sensor", Manufacturer=PixArt, Part number IPS=N.A.
U3: "1.6 A Single-cell Li-Ion/Polymer Battery Charger", Manufacturer=Skyworks, Manufacturer Part Number=AAT3693IDH-AA-T1, Part number IPS=N.A., Supplier Part Number 1=863-1512-1-ND
U4: library part NCP114AMX330TBG, "300 mA CMOS Low Dropout Regulator", Manufacturer="ON Semiconductor", Part number IPS=N.A., Supplier Part Number 1=NCP114AMX330TBGOSCT-ND
U5: "1.8V 200MA INDUCTOR BUILT-IN PFM STEP", Manufacturer="Torex Semiconductor", Manufacturer Part Number=XCL210C181GR-G, Part number IPS=N.A., Supplier Part Number 1=893-1251-1-ND
U7 U8 U9 U10: "2A High Side Load Switch, 67mO", Manufacturer=Microchip, Part number IPS=N.A., Supplier Part Number 1=576-3340-1-ND
X1: library part XTAL_SMD2016_32MHz_8pF_General, "XTAL SMD 2016, 32MHz, Cl=8pF, Total Tol: ±40ppm", Part number IPS=N.A.
X2: library part XTAL_SMD2012_32.768kHz_9pF_NDK, "XTAL SMD 2012, 32.768kHz, 9pF, ±20ppm", Manufacturer=NDK, Manufacturer Part Number="NX2012SA 32.768KHz  S1-4085-xx20-9", Part number IPS=N.A.

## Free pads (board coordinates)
  round 6 on Mech16: 0(-10,67.2) 0(35,35.7)
  round 3.55 hole 3.55 unplated: 0(-8.216,73.175) 0(5,13.02)
  round 5 hole 5 unplated: 0(11.784,40.175)
  round 5.5 hole 3.2: 0(29.684,73.175)
  round 0.35 on Mech16: ""(23.112,35.547) ""(23.112,36.047) ""(23.112,36.547) ""(23.112,37.047) ""(23.112,37.547) ""(24.862,33.797) ""(24.862,39.297) ""(25.362,33.797) ""(25.362,39.297) ""(25.862,33.797) ""(25.862,39.297) ""(26.362,33.797) ""(26.362,39.297) ""(26.862,33.797) ""(26.862,39.297) ""(27.362,33.797) ""(27.362,39.297) ""(27.862,33.797) ""(28.612,34.547) ""(28.612,35.047) ""(28.612,35.547) ""(28.612,36.047)

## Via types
v1: diameter 0.5, hole 0.25, Top Layer to Bottom Layer, tented both sides, 311 vias
v2: diameter 0.35, hole 0.15, Top Layer to Mid-Layer 1, tented both sides, 102 vias
v3: diameter 0.35, hole 0.15, Top Layer to Mid-Layer 1, tented top, 26 vias
v4: diameter 0.61, hole 0.305, Top Layer to Mid-Layer 1, tented both sides, 3 vias
v5: diameter 0.61, hole 0.305, Top Layer to Bottom Layer, tented both sides, 2 vias

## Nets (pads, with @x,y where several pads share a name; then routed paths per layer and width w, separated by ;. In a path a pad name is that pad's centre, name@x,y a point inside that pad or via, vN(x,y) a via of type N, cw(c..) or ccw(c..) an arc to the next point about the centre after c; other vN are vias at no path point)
ANT: C23.1 C27.2 | length 30
  Top Layer w1.27: 33.274,35.506 33.274,33.728 34.036,32.966 35.213,32.966 36.223,33.976 ccw(c-57.806,37.826) 34.026,58.393
D*_N: D1.2 J1.2 R5.2 TP2.1 | length 11.5
  Bottom Layer w0.165: 11.227,44.722 ccw(c11.604,44.722) 11.338,44.456 12.738,43.055 ccw(c13.37,43.687) 13.37,42.794 13.614,42.794 cw(c13.614,42.053) 14.138,42.577 14.335,42.38 cw(c13.909,41.954) D1.2@14.511,41.954 14.92,42.362 cw(c15.977,41.305) 15.977,42.8 18.573,42.8 ccw(c18.757,42.984) 18.757,42.724 R5.2@18.867,42.724 18.867,42.567 TP2.1@18,41.7 ; 11.231,44.722 J1.2@11.231,45.448 J1.2@11.231,45.597
D*_P: D1.3 J1.3 R6.2 TP3.1 | length 10.6
  Bottom Layer w0.165: J1.3@11.881,45.448 11.881,44.588 ccw(c12.288,44.588) 12,44.3 ; 12,44.3 12.992,43.308 ccw(c13.37,43.687) 13.37,43.152 13.614,43.152 ccw(c13.614,43.827) 14.092,43.349 14.354,43.612 ccw(c13.974,43.992) D1.3@14.511,43.992 ; D1.3@14.511,44.004 14.92,43.596 ccw(c15.977,44.653) 15.977,43.158 18.573,43.158 cw(c18.757,42.974) 18.757,43.234 R6.2@18.867,43.234 18.867,43.333 TP3.1@18,44.2
D_N: R5.1 U1.AD4 | length 13.7
  Top Layer w0.165: v1(23.536,32.332) 23.612,32.408 U1.AD4@23.612,33.297
  Bottom Layer w0.165: R5.1@19.437,42.724 19.546,42.724 ccw(c19.546,42.984) 19.73,42.8 20.14,42.8 cw(c20.14,41.53) 21.41,41.53 21.41,35.82 ccw(c24.308,35.82) 22.259,33.771 23.536,32.494 v1(23.536,32.332)
D_P: R6.1 U1.AD6 | length 14.4
  Top Layer w0.165: U1.AD6@24.112,33.297 24.112,32.408 v1(24.188,32.332)
  Bottom Layer w0.165: R6.1@19.437,43.234 19.546,43.234 cw(c19.546,42.974) 19.73,43.158 20.14,43.158 cw(c20.14,41.53) 21.768,41.53 21.768,35.82 ccw(c24.308,35.82) 22.512,34.024 v1@24.196,32.34
DEC1: C5.1 U1.C1 | length 2
  Top Layer w0.25: C5.1@20.86,39.398 21.741,39.398 22.342,38.797 U1.C1@22.612,38.797
DEC3: C11.1 U1.D23 | length 2.6
  Top Layer w0.15: U1.D23@28.612,38.547 28.617,38.547 28.942,38.872 29.212,38.872 30.077,39.738 30.077,40.281 C11.1@30.128,40.281
DEC4_6: C10.2 C15.2 C16.1 L3.1 U1.B5 U1.E24 | length 16.1
  Top Layer w0.15: U1.E24@29.112,38.297 29.112,38.355 30.354,39.597 C10.2@30.449,39.597 ; C10.2@30.449,39.646 30.635,39.46 v1(30.635,39.087)
  Top Layer w0.25: C15.2@22.562,42.157 L3.1@22.562,43.922 ; C15.2@22.837,42.157 22.837,40.66 23.266,40.23 v1(23.698,40.23) 23.741,40.188 23.741,39.436 23.862,39.315 U1.B5@23.862,39.297
  Bottom Layer w0.25: v1(23.698,40.23) 23.698,40.357 24.183,40.843 29.39,40.843 30.635,39.597 v1(30.635,39.087)
EN: J2.10 R12.1 U7.4 U8.4 U9.4 U10.4 | length 24.1
  Top Layer w0.127: v1(2.235,2.859) 3.44,4.064 v1(5.055,4.064) 6.782,4.064 v1(7.442,3.404) 7.442,4.902 v1(7.899,5.359) ; J2.10@10.3,1.2 10.312,1.212 v1(10.312,2.847)
  Mid-Layer 1 w0.127: v1(7.442,3.404) 9.756,3.404 v1(10.312,2.847)
  Bottom Layer w0.127: U7.4@2.218,2.076 2.235,2.093 v1(2.235,2.859) ; v1(5.055,4.064) 5.055,2.652 5.141,2.565 U8.4@5.141,2.076 ; R12.1@7.012,10.246 7.407,10.246 7.899,9.754 v1(7.899,5.359) ; v1(7.442,3.404) 8.074,2.772 U10.4@8.074,2.076 ; v1(10.312,2.847) 10.767,2.847 11.024,2.591 11.024,2.093 U9.4@11.006,2.076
